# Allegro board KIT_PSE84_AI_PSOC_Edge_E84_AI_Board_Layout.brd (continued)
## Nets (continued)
GND_EARTH: C13.1 J1.SH1 J1.SH2 J1.SH3 J1.SH4 J2.SH1 J2.SH2 J2.SH3 J2.SH4 R7.1
GND_SIGNAL: C1.1 C3.1 C4.1 C5.1 C6.1 C7.1 C8.1 C9.1 C11.1 C12.2 C13.2 C14.2 C16.2 C17.2 C21.2 C28.2 C30.2 C31.2 C35.2 C36.2 C37.2 C38.2 C39.2 C40.2 C41.2 C42.2 C43.2 C44.2 C45.2 C46.2 C47.2 C48.2 C49.2 C50.2 C51.2 C52.2 C53.2 C54.2 C55.2 C56.2 C57.2 C58.2 C59.1 C60.1 C61.2 C62.2 C63.1 C64.2 C65.2 C66.2 C67.2 C68.2 C69.2 C70.2 C71.2 C72.1 C73.2 C74.2 C75.2 C76.2 C77.2 C78.2 C79.2 C80.2 C81.2 C82.2 C83.2 C84.2 C85.2 C86.2 C87.2 C88.2 C89.2 C92.2 C93.2 C94.2 C95.2 C96.2 C97.2 C98.2 C99.2 C100.2 C101.2 C102.2 C103.2 C104.2 C107.2 C108.2 C109.2 C110.2 C111.2 C112.2 C113.2 C114.2 C115.2 C116.2 C118.2 C123.2 C124.2 C126.2 C136.2 C137.2 C138.2 C139.2 C140.2 C141.2 C142.2 C143.2 C144.2 C145.2 C146.2 C147.2 C148.2 C149.2 C150.2 C151.2 C152.2 C153.2 C154.2 C155.2 C156.2 C157.2 C158.2 C159.2 C160.2 C161.2 C162.2 C163.2 C164.2 C165.2 C166.2 C167.2 C168.2 C169.2 C170.2 C171.2 C172.2 C173.2 C174.2 C175.2 C176.2 C177.2 C178.2 C179.2 C180.2 C182.2 C183.2 C184.2 C185.2 C186.2 C189.2 C191.2 C194.2 C196.2 C197.2 C200.2 C203.1 C204.2 C205.2 D1.A D2.A D4.A D15.A J1.A1 J1.A12 J1.B1 J1.B12 J2.A1 J2.A12 J2.B1 J2.B12 J3.2 J3.SH1 J3.SH2 J4.3 J4.5 J4.7 J4.9 J5.6 J7.1 J7.SH1 J7.SH2 J8.SH1 J8.SH2 J10.3 J10.6 J10.9 J10.12 J10.15 J10.SH1 J10.SH2 J12.G1 J12.G2 J12.G3 J14.20 J16.3 J17.4 J17.SH1 J17.SH2 J17.SH3 J17.SH4 L2.1 L3.1 L6.1 L7.1 LED4.K(CATHODE) LED5.K(CATHODE) Q3.1 Q3.4(S) Q7.S Q8.S Q9.S Q10.S Q11.S R3.2 R4.2 R7.2 R11.2 R16.2 R22.1 R24.1 R27.1 R73.1 R77.2 R80.2 R84.2 R86.2 R110.1 R126.1 R135.1 R155.2 R173.1 R187.1 R191.1 R211.1 R212.1 R213.1 R214.1 R215.1 R216.2 SW2.3 SW2.4 SW3.3 SW3.4 TP2.1(TP) TP10.1(TP) TP17.1(TP) TP47.1(TP) U1.A9 U1.B5 U1.B13 U1.C8 U1.C10 U1.C11 U1.C12 U1.C13 U1.D3 U1.D7 U1.D9 U1.D11 U1.D12 U1.D13 U1.E8 U1.E12 U1.F3 U1.G13 U1.H3 U1.H12 U1.J13 U1.K12 U1.L3 U1.L8 U1.L13 U1.N3 U1.N10 U1.R7 U2.5 U2.7 U2.8 U2.9 U2.25 U2.43 U2.45 U2.58 U2.62 U2.63 U2.H U3.B3 U3.C1 U3.E5(VSSQ_2) U4.B3 U5.A1 U5.A2 U5.A3 U5.A4 U5.A5 U5.A6 U5.A7 U5.A8 U5.A9 U5.B3 U5.B4 U5.B8 U5.B9 U5.C9(VSSRF_9) U5.D9 U5.E9 U5.H9 U5.J9 U5.K1 U5.K9 U5.L9 U5.M7 U5.M9 U6.1 U6.7 U7.5 U8.4 U8.5 U9.4 U9.5 U10.4 U10.5 U13.8 U15.3(VSS) U15.H U18.6 U18.7 U19.3 U20.B1 U20.C3 U21.10 U22.4(VSS) U23.3(VSS) U23.H U24.2 U25.10 U25.12 U25.13 U25.19 U25.21 U25.24 U25.26 U25.27 U25.29 U25.39 U25.44 U25.49 U25.51 U25.52 U25.53 U25.55 U25.56 U25.58 U25.59 U25.60 U25.61 U25.66 U25.67 U25.68 U25.69 U25.70 U25.71 U25.72 U26.3(VSS) U26.H U27.3(VSS) U27.H U28.1 U28.16 U28.18 U28.20 U28.25 U28.29 U28.H U29.1 U29.6 U30.3 U31.2 U33.2 U33.5 U34.2 U34.5 U34.H U35.2 U35.5 U36.3 U40.4 Y1.2 Y1.4(GND_2) Y3.2 Y4.G
VBAT_IN: C9.2 C186.1 D15.K(CATHODE) J3.1 TP8.1(TP) U23.4 U23.6
VCC_1V8: C73.1 C75.1 C81.1 C83.1 C89.1 C196.1 FB1.1 FB2.1 FB4.1 FB5.1 FB6.1 FB7.1 J17.3 R124.1 R225.1 TP50.1(TP) U33.1(OUT)
VCC_3V3: C77.1 C191.1 FB3.1 J17.2 TP51.1(TP) U35.1(OUT)
VCC_IN: C3.2 C7.2 C8.2 C14.1 C16.1 L1.1 U23.1 U26.1 U27.1 U29.5 U29.7
VDD_1V8: C5.2 C61.1 C62.1 C63.2 C64.1 C65.1 C66.1 C67.1 C68.1 C70.1 C71.1 C96.1 C97.1 C98.1 C99.1 C111.1 C112.1 C113.1 C114.1 C197.1 C200.1 C204.1 J5.1 R2.1 R5.2 R6.1 R8.2 R9.1 R76.1 R79.1 R85.2 R112.2 R114.2 R123.2 R192.2 R193.2 R194.2 R195.2 R196.2 R203.2 R204.1 R205.1 R208.2 R224.1 TP49.1(TP) U3.B4 U3.D1 U3.E4 U4.B4 U6.6(VDDIO) U6.8 U7.2(VDD) U7.4 U8.2(VDD) U18.5(VDDIO) U18.8 U18.12 U20.B2 U20.B3(VDDIO) U20.C1 U22.3 U28.2 U28.3 U31.5 U34.3(VOUT) U34.8 U40.8(VCCB) Y3.1 Y3.4(VDD) Y4.P(VDD)
VDD_3V3: C27.1 C28.1 C94.1 C95.1 C107.1 C108.1 C109.1 C110.1 C194.1 C203.2 J7.2 J14.19 R15.1 R153.2 R159.2 R188.2 R197.2 R206.2 R207.2 R217.2 TP48.1(TP) U13.11 U25.22 U25.23 U28.17 U28.28 U33.3 U33.4 U40.1
VDD_5V: C6.2 C12.1 C17.1 C21.1 C30.1 C31.1 C101.1 C102.1 C103.1 C104.1 C182.1 C183.1 C184.1 C189.1 C205.1 J16.1 J17.1 LED3.4 R10.1 R174.2 R190.2 R209.2 R210.2 TP12.1(TP) U13.6 U13.7 U13.9(PVIN) U15.6 U21.12 U28.21 U28.24 U29.3(VOUT) U34.4 U34.6 U35.3 U35.4
VDDA_RADAR: C76.1 FB2.2 U5.J1
VDDD_RADAR: C74.1 FB1.2 U5.H1
VDDIO_RADIO: C93.1 R103.1 R104.1 R105.1 R106.1 R107.1 R108.1 R109.1 R203.1 U25.11
VDDLF_RADAR: C78.1 FB3.2 U5.M3
VDDPLL_RADAR: C84.1 FB6.2 U5.M4
VDDRF_RADAR: C85.1 C86.1 C87.1 C88.1 FB7.2 U5.F9 U5.G9 U5.M1
VDDVCO_RADAR: C82.1 FB5.2 U5.M6
A_IO_P13_0: J17.20 U1.G8
A_IO_P13_1: J17.18 U1.G9
A_IO_P13_2: J17.16 U1.G10
A_IO_P13_3: J17.14 U1.F15
A_IO_P13_4: J17.12 U1.G11
A_IO_P13_5: J17.10 U1.G14
A_IO_P13_6: J17.8 U1.H11
A_IO_P13_7: J17.6 U1.H15
A_IO_P15_0: J17.5 U1.L15
A_IO_P15_1: J17.7 U1.K13
A_IO_P15_2: J17.9 U1.M15
A_IO_P15_3: J17.11 U1.K9
A_IO_P15_4: J17.13 U1.N15
A_IO_P15_5: J17.15 U1.K10
A_IO_P15_6: J17.17 U1.P15
A_IO_P15_7: J17.19 U1.K11
ALT_SER_INT_CONFIG_1: R76.2 R77.1 TP66.1(TP) U1.R15
ALT_SER_INT_CONFIG_2: R79.2 R80.1 TP65.1(TP) U1.M12
AMIC1_CTB_INN: C121.2 R132.2 U1.H13
AMIC1_CTB_INP: C116.1 R128.2 R227.2 U1.H10
AMIC1_CTB_OUT: C121.1 C122.1 R133.2 U1.H9
AMIC1_CTB_REF: R227.1 U1.J10
AMIC2_CTB_INN: C129.2 R141.2 U1.J15
AMIC2_CTB_INP: C124.1 R137.2 R228.2 U1.J9
AMIC2_CTB_OUT: C129.1 C130.1 R142.2 U1.K15
AMIC2_CTB_REF: R228.1 U1.J14
AMIC_1V8: C118.1 C126.1 R124.2 R125.1 R134.1 R224.2 U9.2(VDD) U10.2(VDD)
BOOT: R189.1 U1.N8
BT_DEV_WAKE: R106.2 U1.D15 U25.40
BT_HOST_WAKE: R107.2 U1.D14 U25.41
BT_REG_ON: R105.2 U1.E14 U25.8
BT_UART_CTS_MCU_RTS: TP55.1(TP) U1.A14 U25.48
BT_UART_RTS_MCU_CTS: TP56.1(TP) U1.C15 U25.47
BT_UART_RX_MCU_TX: TP53.1(TP) U1.A13 U25.45
BT_UART_TX_MCU_RX: TP54.1(TP) U1.B15 U25.46
DISP_VDD_3V3: C136.1 J10.1 J10.2 R153.1
DSI_CLK_N: J10.11 R66.1
DSI_CLK_P: J10.10 R67.1
DSI_DATA0_N: J10.8 R70.1
DSI_DATA0_P: J10.7 R71.1
DSI_DATA1_N: J10.14 R68.1
DSI_DATA1_P: J10.13 R69.1
ECO_IN: C55.1 U1.B6 Y1.1
ECO_OUT: C56.1 U1.F8 Y1.3
EXT_CLK: R218.2 U1.P4
I2C_SCL_1V8: R32.1 R223.2 U1.H7 U2.38 U6.4 U18.13 U22.2 U28.10
I2C_SCL_3V3: J7.4 J10.5 J14.17 J16.2 R207.1 U1.M9
I2C_SDA_1V8: R31.1 R220.2 U1.J8 U2.39 U6.3 U18.14 U22.1 U28.9
I2C_SDA_3V3: J7.3 J10.4 J14.18 J16.4 R206.1 U1.R9
I2S_TX_FSYNC: U1.E5 U28.6
I2S_TX_MCK: U1.D4 U28.8
I2S_TX_SCK: U1.K7 U28.7
I2S_TX_SD: U1.E4 U28.5
I3C_SCL: R205.2 R222.2 TP71.1(TP) U1.M4
I3C_SDA: R204.2 R221.2 TP72.1(TP) U1.L6
IMU_INT1: U1.L5 U18.4
IMU_INT2: U1.P5 U18.9
JTAG_SEL: R109.2 R110.2 U25.57
KP_USB_DM: J1.A7 J1.B7 R28.1 U19.1
KP_USB_DP: J1.A6 J1.B6 R26.1 U19.2(K2)
KP_VBUS: C4.2 D1.K(CATHODE) J1.A4 J1.A9 J1.B4 J1.B9(VBUS_4) R18.2 TP1.1(TP) U27.4 U27.6
LPO_OUT_2FY: R182.2 U25.30
MAG_INT: U1.R5 U20.A1
MCU_UART_RX_KP3_TX: U1.R2 U2.20
MCU_UART_TX_KP3_RX: R29.1 U1.P2 U2.21
MCU_VDD_3V3: C139.1 C140.1 C141.1 C179.1 C180.1 R154.2 R197.1 U1.B11 U1.D10 U1.R10
MEMORY_RST: R208.1 U1.K5 U3.A4
P5LP1_2: SW3.1 SW3.2 U2.13
P5LP1_4: R30.2 U2.15
P5LP2_2: U2.64
P5LP2_3: U2.65
P5LP2_4: U2.66
P5LP_SIO_VREF: R21.2 R22.2 U2.48
P5LP_SWCLK: TP19.1(TP) U2.12
P5LP_SWDIO: TP20.1(TP) U2.11
P5LP_VCCD: C44.1 C45.1 U2.26 U2.57
P5LP_VDD: C35.1 C36.1 C37.1 C38.1 C39.1 C40.1 C41.1 C42.1 C46.1 C47.1 C48.1 C49.1 C50.1 C51.1 R18.1 R25.1 TP16.1(TP) U2.17 U2.24 U2.35 U2.44 U2.52 U2.59 U2.67
P5LP_XRES: TP18.1(TP) U2.10(X\R\E\S\)
P11_1: TP70.1(TP) U1.E11 U40.7
P11_1_IN_3V3: J14.13 U40.2
P16_0: J14.6 U1.M11
P16_1: J14.5 U1.R13
P16_2: J14.8 U1.N11
P16_3: J14.7 U1.L11
P16_4: J14.10 U1.P11
P16_5: J14.9 U1.L10
P16_6: J14.12 U1.R11
P16_7: J14.11 U1.M10
P17_2: J14.15 U1.R8
P17_3: J14.16 U1.P9
P17_4: J14.14 U1.P8
P17_5: J14.1 J14.3 U1.N9
P17_7: J14.2 J14.4 U1.L9
PDM_CLK: R88.2 R92.2 U1.E7
PDM_DATA: R87.2 R91.2 U1.G6
PE84_RST_L: C58.1 J4.10 R72.2 SW2.1 SW2.2 U1.D8 U2.3
PE84_SWCLK: J4.4 R200.2 U1.R6 U2.47
PE84_SWDIO: J4.2 R199.2 U1.P6 U2.46
PE84_SWO: J4.6 R201.2 U1.M6
PE84_TDI: J4.8 R202.2 U1.N6
PE84_USB_CC1: J2.A5 U21.1 U36.1
PE84_USB_CC2: J2.B5 U21.2 U36.2(K2)
PE84_USB_CF: R2.2 TP3.1(TP) U1.K8 U21.6(\V\C\O\N\N\_\F\A\U\L\T\)
PE84_USB_DIR: R6.2 TP5.1(TP) U1.M5 U21.11
PE84_USB_DM: J2.A7 J2.B7 U1.P7 U30.1
PE84_USB_DP: J2.A6 J2.B6 U1.N7 U30.2(K2)
PE84_USB_ID: R9.2 TP7.1(TP) U1.N5 U21.9 U31.1
PE84_USB_OUT1: R8.1 TP6.1(TP) U1.L4 U21.7
PE84_USB_OUT2: R5.1 TP4.1(TP) U1.N4 U21.8
PE84_VBUS: C1.2 C11.2 C185.1 D2.K(CATHODE) J2.A4 J2.A9 J2.B4 J2.B9(VBUS_4) R1.2 R219.2 TP9.1(TP) U15.1 U26.6
PE84_VCCD: C152.1 C165.1 C166.1 C167.1 C168.1 C169.1 L5.2 TP45.1(TP) U1.B1 U1.B9 U1.B12 U1.E9 U1.F11 U1.H4 U1.M8
PE84_VDDA: C146.1 C147.1 C148.1 C149.1 C170.1 FB9.2 U1.G12 U1.H14 U1.J11 U1.J12 U1.L12
PE84_VTARG: C54.1 C138.1 C150.1 C151.1 C175.1 D4.K(CATHODE) FB8.1 FB10.2 FB11.2 J4.1 R21.1 R23.1 R29.2 R31.2 R32.2 R72.1 R196.1 R198.1 R199.1 R200.1 R201.1 R202.1 R226.1 U1.A10 U1.A11 U1.B10 U1.D6
PSEN_INT: R84.1 U1.E10 U6.5
RF_OUT: C90.1 C198.1 U25.50
ROSC_IN_80MHZ: R102.2 U5.M2
RSPI_CLK: U1.L7 U5.B1
RSPI_CS: U1.C3 U5.G1
RSPI_IRQ: U1.N12 U5.C1
RSPI_MISO: U1.K6 U5.E1
RSPI_MOSI: U1.C5 U5.D1
RXRES_L: R101.1 U1.R12
SERIAL_INT0: J5.5 R192.1 U1.L14
SERIAL_INT1: J5.4 R193.1 U1.M13
SERIAL_INT2: J5.3 R194.1 U1.M14
SERIAL_INT3: J5.2 R195.1 U1.N13
SMIF0_CLKP: R61.1 U4.B2
SMIF0_CS: R112.1 U1.K4 U4.C2
SMIF0_DATA0: R45.1 U4.D3
SMIF0_DATA1: R47.1 U4.D2
SMIF0_DATA2: R49.1 U4.C4
SMIF0_DATA3: R51.1 U4.D4
SMIF1_CLKN: R63.2 U3.B1
SMIF1_CLKP: R62.2 U3.B2
SMIF1_CS: R114.1 U1.C4 U3.A3
SMIF1_DATA0: R46.2 U3.D3
SMIF1_DATA1: R48.2 U3.D2
SMIF1_DATA2: R50.2 U3.C4
SMIF1_DATA3: R52.2 U3.D4
SMIF1_DATA4: R54.2 U3.D5
SMIF1_DATA5: R56.2 U3.E3
SMIF1_DATA6: R58.2 U3.E2
SMIF1_DATA7: R60.2 U3.E1
SMIF1_RWDS: R65.2 U3.C3
USB_DEV_EN: Q3.5 R191.2 R219.1 U26.4 U31.4(Y)
USB_HOST_EN: Q3.2 R173.2 U15.4 U31.3 U31.6
USB_V_SENSE: R25.2 R27.2 U2.19
USER_BTN: C57.1 R198.2 SW1.1 SW1.2 U1.P3
USER_LED1: Q7.G R211.2 U1.C14
USER_LED2: Q8.G R212.2 U1.B14
USER_LED_RGB_B: Q11.G R215.2 U1.P12
USER_LED_RGB_G: Q10.G R214.2 U1.R14
USER_LED_RGB_R: Q9.G R213.2 U1.P13
USR_RGB_B: Q11.D R165.2
USR_RGB_G: Q10.D R157.1
USR_RGB_R: Q9.D R156.1
VTARG_MEAS: R23.2 R24.2 U2.32
WCO_IN: C60.2 U1.H8 Y2.1
WCO_OUT: C59.2 U1.G7 Y2.2
WL_BT_DEV_WAKE: R103.2 U1.E15 U25.5
WL_HOST_WAKE: R104.2 U1.F13 U25.2
WL_REG_ON: R108.2 U1.F14 U25.9(WL_REG_ON)
WL_SDIO_CLK: R38.2 U25.20
WL_SDIO_CMD: R33.2 U25.15
WL_SDIO_DATA0: R37.2 U25.14
WL_SDIO_DATA1: R36.2 U25.16
WL_SDIO_DATA2: R35.2 U25.17
WL_SDIO_DATA3: R34.2 U25.18
N17461053: TP21.1(TP) U5.M5
N17461288: C72.2 U5.L1
N17462113: C79.1 C80.1 FB4.2 U24.4(VCC)
N17462137: R102.1 U24.3
N17489317: R73.2 SW1.3 SW1.4
N17506591: R85.1 R86.1 U18.1
N17580471: C43.1 U2.53
N17581080: C52.1 U2.42
N17581130: R26.2 U2.22
N17581131: R28.2 U2.23
N17581135: C53.1 U2.31
N17604769: R101.2 U5.F1
N17606878: LED4.A R30.1
N17691977: C92.1 L4.1 U25.25
N17691999: L4.2 U25.28
N17694386: J8.1 U28.22 U28.26
N17694402: J8.2 U28.19 U28.23
N17694449: C100.1 R123.1 U28.31(\R\E\S\E\T\)
N17694464: TP22.1(TP) U28.27
N17694501: TP23.1(TP) U28.30
N17694590: C105.1 TP24.1(TP)
N17694592: C105.2 U28.13
N17694611: C106.2 U28.14
N17694617: C106.1 TP25.1(TP)
N17695662: C115.1 C119.1 R125.2 R126.2 R127.2 R128.1
N17695725: C117.2 R127.1
N17695747: R129.1 U10.1
N17695749: C117.1 R129.2
N17695799: R130.1 U10.3
N17695801: C120.1 R130.2
N17695803: C120.2 R131.1
N17695815: C119.2 C122.2 R131.2 R132.1 R133.1
N17695981: C123.1 C127.1 R134.2 R135.2 R136.2 R137.1
N17696044: C125.2 R136.1
N17696066: R138.1 U9.1
N17696068: C125.1 R138.2
N17696118: R139.1 U9.3
N17696120: C128.1 R139.2
N17696122: C128.2 R140.1
N17696134: C127.2 C130.2 R140.2 R141.1 R142.1
N17699019: C137.1 C142.1 C143.1 C144.1 C145.1 FB8.2 U1.A7 U1.B8 U1.F7 U1.G4 U1.P10
N17699233: FB9.1 R225.2 R226.2
N17699382: L5.1 U1.A12
N17699478: C153.1 C154.1 R154.1 U1.M7
N17699488: C155.1 TP46.1(TP) U1.K14
N17701248: C156.1 C157.1 C158.1 U1.A8(VLDO_SRAM) U1.F12 U1.K3
N17701334: C159.1 U1.C9
N17701356: C160.1 C161.1 C162.1 C163.1 C164.1 FB10.1 U1.A6 U1.B2 U1.E6 U1.E13 U1.N14 U1.R3
N17701674: C171.1 C172.1 C173.1 C174.1 FB11.1 U1.E3 U1.G3 U1.J3 U1.M3
N17701770: R155.1 U1.J6
N17701786: C176.1 C177.1 C178.1 U1.B7 U1.C6 U1.C7
N17708163: R33.1 U1.J5
N17708171: R34.1 U1.F5
N17708201: R35.1 U1.F4
N17708259: R36.1 U1.G5
N17708293: R37.1 U1.D5
N17708327: R38.1 U1.H5
N17708399: TP69.1(TP) U1.P14
N17708861: R45.2 U1.N2
N17708863: R46.1 U1.C2
N17708893: R47.2 U1.P1
N17708895: R48.1 U1.C1
N17708925: R49.2 U1.N1
N17708927: R50.1 U1.D2
N17708957: R51.2 U1.M2
N17708959: R52.1 U1.D1
N17708991: R54.1 U1.F2
N17709023: R56.1 U1.E2
N17709055: R58.1 U1.G2
N17709075: R60.1 U1.H2
N17709105: R61.2 U1.M1
N17709107: R62.1 U1.E1
N17709123: R63.1 U1.F1
N17709155: R65.1 U1.H1
N17709188: R66.2 U1.A4
N17709192: R67.2 U1.A5
N17709220: R68.2 U1.A3
N17709224: R69.2 U1.A2
N17709256: R70.2 U1.B4
N17709266: R71.2 U1.B3
N17713209: L1.2 U29.2
N17713383: R10.2 R11.1 U29.4
N17787194: J1.A5 R4.1
N17787196: J1.B5 R3.1
N17852597: R1.1 U21.5
N17861601: LED5.A R159.1
N17865809: U13.2 U13.3 U13.10
N17865831: C27.2 R15.2 R16.1 U13.5
N17879800: U34.1 U34.7
N17892556: R218.1 TP52.1(TP) Y3.3
N17899696: R187.2 R188.1 R189.2
N17920449: ANT1.1 C91.2 L3.2
N17920453: C90.2 C91.1 L2.2
N17920674: C198.2 C199.1 L6.2
N17920680: C199.2 J12.S(SIG) L7.2
N17936697: D11.A R174.1
N17936707: D11.K(CATHODE) Q3.6
N17937120: D14.A R190.1
N17937130: D14.K(CATHODE) Q3.3
N17947353: R182.1 Y4.O
N17989965: R88.1 U8.3
N17989977: R87.1 U8.1
N17990624: R92.1 U7.3
N17990639: R91.1 U7.1
N18038435: LED1.A R209.1
N18038437: LED2.A R210.1
N18038455: LED1.K(CATHODE) Q7.D
N18038457: LED2.K(CATHODE) Q8.D
N18039037: LED3.1(RED) R156.2
N18039056: LED3.2 R157.2
N18039072: LED3.3 R165.1
N18042757: R216.1 R217.1 U40.5
N18094677: R220.1 R221.1 U20.A2
N18094686: R222.1 R223.1 U20.A3
N18095156: C69.1 U20.C2

Pads without a net: ANT1 2; J1 A8 B8; J2 A8 B8; U1 F6 F9 F10 H6 J1 J2 J4 J7 K1 K2 L1 L2 R4; U2 1 2 4 6 14 16 18 27 28 29 30 33 34 36 37 40 41 49 50 51 54 55 56 60 61 68; U3 A2 A5 B5 C2 C5; U4 A2 A3 A4 A5 B1 B5 C1 C3 C5 D1 D5 E1 E2 E3 E4 E5; U6 2; U13 1 4; U15 2 5; U18 2 3 10 11; U21 3 4; U23 2 5; U24 1; U25 1 3 4 6 7 31 32 33 34 35 36 37 38 42 43 54 62 63 64 65; U26 2 5; U27 2 5; U28 4 11 12 15 32; U40 3 6; Y4 N

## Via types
v1: diameter 0.406, hole 0.203, TOP to BOTTOM, 208 vias
v2: diameter 0.457, hole 0.203, TOP to BOTTOM, 222 vias
v3: diameter 0.508, hole 0.254, TOP to BOTTOM, 318 vias
v4: diameter 0.45, hole 0.2, TOP to BOTTOM, 5 vias

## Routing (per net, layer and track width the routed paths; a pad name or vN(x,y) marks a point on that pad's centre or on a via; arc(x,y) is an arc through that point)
GND_EARTH: length 39.4
  TOP w0.305: 5.31,1.94 J2.SH3 ; J2.SH3 6.01,3.05 ; J2.SH3 6.72,1.94 ; J2.SH3 6.01,0.84 ; 6.01,4.87 J2.SH1 5.31,6.12 ; J2.SH4 15.36,1.94 ; J2.SH4 13.95,1.94 ; J2.SH4 14.65,0.84 ; J2.SH4 14.65,3.05
  BOTTOM w0.305: 29.28,6.12 J1.SH2 ; J1.SH2 29.98,4.87 ; J1.SH2 30.69,6.12 ; J1.SH2 29.98,7.38 ; J2.SH1 6.72,6.12 ; J2.SH1 6.01,7.38 ; J2.SH1 5.31,6.12 ; J2.SH1 6.01,4.87 ; J2.SH2 14.65,7.38 ; J2.SH2 15.36,6.12 ; J2.SH2 14.65,4.87 ; J2.SH2 13.95,6.12 ; 21.34,4.87 J1.SH1 ; J1.SH1 22.05,6.12 ; J1.SH1 21.34,7.38 ; J1.SH1 20.64,6.12 ; 6.01,0.84 J2.SH3 ; J2.SH3 5.31,1.94 ; J2.SH3 6.72,1.94 ; J2.SH3 6.01,3.05 ; 20.64,1.94 J1.SH3 ; J1.SH3 21.34,0.84 ; J1.SH3 21.34,3.05 ; J1.SH3 22.05,1.94 ; 14.65,0.84 J2.SH4 ; J2.SH4 14.65,3.05 ; J2.SH4 13.95,1.94 ; J2.SH4 15.36,1.94 ; J1.SH4 29.98,3.05 ; J1.SH4 30.69,1.94 ; J1.SH4 29.28,1.94 ; J1.SH4 29.98,0.84
GND_SIGNAL: length 385.1
  TOP w0.15: U1.D9 25.84,35.26 v1(25.86,35.26) ; v1(23.97,35.27) 23.97,35.24 U1.D7 ; U1.C10 v1(26.52,35.94) ; U1.L8 v1(25.22,30.09) ; U1.E12 v1(27.82,34.64) ; U1.C12 v1(27.82,35.94) ; U1.D11 v1(27.17,35.29) ; U1.E8 v1(25.22,34.64) ; U1.G13 28.45,33.32 v1(28.45,33.38) ; U1.K12 v1(27.82,30.74) ; U1.F3 v1(21.32,33.99) ; U1.D3 v1(21.32,35.29) ; U1.B5 22.62,36.59 v1(22.62,36.59) ; U1.D13 v1(28.47,35.29) ; U1.C11 v1(27.17,35.94) ; U1.H3 v1(21.32,32.04) ; U1.N10 v1(26.52,28.79) ; U1.C13 v1(28.47,35.94) ; U1.J13 v1(28.47,31.39) ; U1.C8 v1(25.22,35.94) ; U1.L3 v1(21.32,30.09) ; U1.D12 v1(27.82,35.29) ; U1.N3 v1(21.32,28.79) ; U1.B13 v1(28.47,36.59) ; U1.H12 v1(27.82,32.04) ; U1.L13 v1(28.47,30.09)
  TOP w0.178: R86.2 22.53,21.94 22.72,22.14 v3(22.72,22.68) ; C86.2 21.59,18.29 22.36,19.06 22.41,19.06 v3(22.72,19.37) ; C200.2 28.81,50.42 28.8,50.42 28.8,50.28 28.45,49.92 28.45,49.1 ; C185.2 12.92,16.21 12.95,16.19 C1.1 13.9,16.19 13.95,16.14 U15.3 ; C185.2 12.22,16.21 11.97,16.45 v3(11.5,16.45) ; C185.2 12.42,15.47 13.31,14.58 U31.2 ; C5.1 16.18,14.33 v3(15.89,14.05)
  TOP w0.229: C76.2 25.55,20.83 v3(25.81,20.58) ; v3(22.48,12.57) 22.07,12.57 21.84,12.35 C89.2 ; U6.7 33.74,20.29 v3(34.04,19.99) ; C77.2 17.53,15.5 17.48,15.55 17.48,15.64 v3(17.41,15.71) ; U25.56 23.52,46.19 v3(23.92,45.79) ; 30.54,17.83 30.1,17.39 U5.A3 U5.B3 ; J3.SH2 3.65,9.73 v3(3.93,10.01) ; v3(19.56,16.71) 19.05,16.71 U24.2 ; C73.2 28.88,22.55 28.5,22.94 27.89,22.94 27.86,22.96 C75.2 27.84,22.63 27.56,22.35 26.14,22.35 25.91,22.58 v3(25.78,22.58) ; v3(29.75,13.11) 29.41,13.44 29.41,14.1 29.12,14.39 U5.A9 ; v3(26.99,13.72) 26.93,13.78 U5.D9 U5.E9 ; v4(7.42,27.53) 7.14,27.81 C104.2 ; v3(20.95,50.67) 21.32,50.31 U25.52 ; U5.B8 U5.A7 28.83,15.39 29.08,15.64 v3(29.08,16.11) 28.86,15.89 U5.A6 U5.A5 ; LED4.K v3(35.2,5.44) ; v3(30.4,17.78) 29.9,17.78 29.29,18.39 U5.A1 U5.A2 ; C68.2 16.27,25.2 16.04,25.43 v1(15.62,25.43) ; C87.2 25.33,11.24 v3(25.78,10.8) 25.78,10.85 26.13,11.2 C88.2 ; C93.2 20.85,43.46 21.07,43.69 U25.12 ; v3(25.96,50.85) 25.63,50.52 25.53,50.52 25.32,50.3 U25.44 ; v3(19.38,5.03) 19.16,5.25 Q3.1 ; v3(16.94,54.28) 17.37,54.71 J10.3 ; U22.4 32.54,14.65 32.18,15.01 C71.2 ; v3(34.68,51.91) 34.57,51.79 C126.2 ; 7.14,25.81 6.59,25.81 6.31,26.08 v3(5.84,26.08) ; C118.2 4.17,52.13 4.57,51.73 v3(4.57,51.26) ; 8.76,24.74 9.27,24.74 9.27,24.43 9.4,24.31 v3(9.4,24.24) ; U25.12 21.47,43.47 21.32,43.32 U25.13 ; U25.12 21.82,43.69 v3(22.62,44.49) 22.42,44.69 U25.10 ; C12.2 13.38,8.46 v3(13.87,7.98) ; v3(21.56,51.11) 21.56,50.91 21.82,50.66 U25.51 ; v3(21.95,14.17) 22.17,14.39 U5.M9 U5.M7 ; J10.6 14.37,57.05 v3(13.69,57.74) ; v3(13.18,25.38) 12.83,25.02 11.63,25.02 C58.2 ; U5.J9 U5.H9 24.77,14.23 v3(24.77,13.85) ; v1(15.62,26.95) 15.67,27 C69.2 ; v3(16.95,7.71) 16.95,7.61 16.86,7.52 Q3.4 ; U5.B4 U5.A4 28.83,16.89 28.93,16.79 v3(28.93,16.77) ; v3(22.72,20.64) 22.72,20.74 23.08,21.1 C72.1 ; v3(24.25,19.37) 23.91,19.04 23.91,18.76 23.93,18.74 U5.K1 ; C60.1 30.22,39.19 30.75,38.66 31.24,38.66 v3(31.57,38.33) ; v3(19.97,11.66) 20.13,11.49 C82.2 ; v3(15.21,21.77) 15.21,22.06 15.44,22.29 C57.2 ; v3(25.22,44.49) 25.22,43.77 25.32,43.67 U25.21 ; U25.55 23.52,46.69 v3(23.92,47.09) ; 20.95,16.36 C78.2 ; SW2.3 14.67,27.56 14.86,27.37 v1(14.86,26.95) ; SW2.3 SW2.4 ; SW2.3 14.97,28.38 15.28,28.69 16.66,28.69 16.89,28.46 C67.2 17.32,27.99 17.45,27.86 U20.B1 ; LED5.K 4.55,7.65 v3(5.08,8.18) ; v1(14.5,17.59) 14.97,18.06 C6.1 15.27,18.01 ; U25.29 26.72,44.69 v3(26.52,44.49) 26.52,44.02 26.82,43.72 U25.24 ; v3(19.71,10.16) C83.2 18.95,10.16 18.22,9.43 C81.2 ; Y1.4 20.83,40.58 20.8,40.61 20.13,40.61 20.09,40.65 ; U20.C3 16.69,25.93 v1(15.62,25.93) ; C97.2 10.85,40.15 11.97,39.03 v3(12.73,39.03) 12.73,39.8 12.67,39.85 C96.2 ; v3(19.36,24.8) 19.36,24.77 ; 19.36,24.77 19,24.41 C64.2 19,24.09 18.6,23.7 U18.7 ; 19.36,24.77 19.7,24.42 C63.1 19.7,24.31 19.13,23.73 19.13,23.26 U18.6 ; 32.26,53.19 v3(32.26,53.19) ; v3(35.22,20.94) U6.1 ; U3.B3 11.65,35.8 11.34,36.11 v1(11.33,36.11) ; R213.1 30.99,13.25 Q9.S ; U5.A9 U5.B9 U5.C9 ; U5.A9 U5.A8 ; v3(24.96,41.24) 24.96,40.8 25.2,40.56 C177.2 25.59,40.38 25.59,40.39 C95.2 C92.2 27.64,40.26 27.95,40.26 v3(28.28,39.93) 28.3,39.91 28.3,39.9 28.4,39.79 C59.1 27.64,39.22 27.28,39.57 C151.2 C158.2 ; J10.15 5.37,54.64 5.55,54.46 v3(6.02,54.46) ; U25.39 27.82,51.02 ; v3(28.55,43.61) 28.35,43.61 28.27,43.69 U25.27 ; U5.L9 U5.K9 23.93,13.94 v3(24.64,13.23) ; v3(23.92,44.49) 24.32,44.09 U25.19 ; J10.9 11.37,56.6 12.04,57.26 v3(12.04,57.74) ; C180.2 26.68,24.39 26.94,24.65 27.37,24.65 27.46,24.56 v3(27.93,24.56) ; C4.1 27.88,9.22 v3(28.13,8.97) ; Q7.S 31.69,8.31 31.97,8.03 R211.1 31.97,7.03 v3(32.12,6.89) ; Y1.2 23.47,39.58 23.72,39.83 C56.2 24.36,39.83 24.59,39.6 C178.2 24.59,38.69 24.39,38.48 v3(22.12,38.48) ; 20.09,40.65 20.09,40.9 19.86,41.13 v3(19.78,41.13) ; 20.09,40.65 C55.2 ; 10.23,19.49 v3(10.7,19.49) ; v3(28.27,41.83) 27.82,42.29 U25.26 ; J10.12 8.37,54.56 7.84,54.03 v3(7.21,54.03) ; v3(20.32,14.6) 20.32,14.64 20.55,14.87 C84.2 ; J10.SH2 4.37,60.31 4.56,60.5 v3(5.21,60.5) ; v3(6.91,35.05) C99.2 7.08,34.52 7.36,34.8 U3.C1 ; U25.49 22.82,49.3 22.62,49.1 v3(22.62,48.39) ; C85.2 v3(25,10.84) ; J10.SH1 v3(20.37,60.6)
  TOP w0.254: U1.A9 v1(25.87,37.24)
  TOP w0.305: 1.58,21.81 J14.20 1.58,19.85 ; J5.6 34.42,44.64 ; J5.6 34.42,42.63 ; J5.6 33.41,43.64
  L02_GND w0.089: 28.83,31.04 28.83,30.92 28.8,30.89 28.8,30.63 28.83,30.6 28.83,30.51 ; 28.83,34.9 28.79,34.87 28.79,33.67 28.83,33.63 ; 28.85,31.65 28.99,31.65 29.02,31.68 29.28,31.68 29.31,31.65 29.54,31.65 ; 22.2,36.91 22.11,36.91 22.1,36.92 21.83,36.92 21.81,36.91 21.46,36.91 ; 26.21,36.83 26.19,36.81 26.19,36.21 ; 25.55,30.43 26.37,30.43 26.4,30.4 27.4,30.4 ; 27.38,31.09 27.38,31.14 27.49,31.25 27.49,31.66 27.58,31.75 ; 27.41,29.11 26.92,29.11 ; 28.14,36.93 28.14,37.57 ; 26.15,29.14 25.73,29.14 25.54,29.33 25.54,29.75 ; 27.48,34.31 26.9,34.31 26.9,34.32 ; 23.09,36.91 24.18,36.91 ; 25.63,36.86 25.54,36.77 25.54,36.38 25.63,36.3 ; 23.05,36.26 24.17,36.26 ; 28.14,34.32 28.14,33.71 ; 26.84,27.18 26.82,27.15 ; 29.43,34.96 28.98,34.96 28.93,34.9 ; 26.15,28.46 24.96,28.46 ; 26.94,28.46 27.55,28.46 ; 22.19,36.26 21.63,36.26
  L02_GND w0.102: 28.14,29.06 28.14,29.23 28.16,29.25 28.16,29.52 28.14,29.55 28.14,29.74 ; 28.04,28.45 28.83,28.45
  L02_GND w0.152: 22.75,36.59 v1(22.62,36.59) ; 27.2,27 27.79,27.59 ; 28.36,27.71 29.01,27.71
  L02_GND w0.305: J5.6 34.42,44.64 ; J5.6 34.42,42.63 ; J5.6 33.41,43.64 ; 1.58,19.85 J14.20 ; J14.20 2.56,20.83 ; J14.20 1.58,21.81
  L03_SIG1 w0.229: v4(8.89,29.01) 8.89,30.68 7.47,32.11 v3(6.17,32.11)
  L04_SIG2 w0.381: v3(1.4,54.33) 3.63,56.57 17.57,56.57 18.71,57.71 22.19,57.71 22.57,57.33 22.57,55.92 23.19,55.3 23.19,54.69 23.62,54.26 32.35,54.26 32.52,54.43 v3(33.07,54.43)
  L05_PWR w0.305: J5.6 34.42,44.64 ; J5.6 33.41,43.64 ; J5.6 34.42,42.63
  BOTTOM w0.089: v1(28.47,31.39) 28.78,31.7 29.57,31.7 29.66,31.79 C149.2 30.14,32.06 30.43,31.76 C155.2
  BOTTOM w0.15: 27.64,4.12 v3(27.64,4.01) ; U8.4 4.38,7.91 4.65,8.18 v3(5.08,8.18)
  BOTTOM w0.152: v3(31.85,28.83) 32.29,28.39 J17.SH2 32.78,28.39 32.9,28.27 32.9,28.13 32.93,28.1 32.93,27.75 32.94,27.75 32.94,27.67 32.78,27.51 J17.4
  BOTTOM w0.178: C36.2 19.3,20.65 19.3,20.64 U2.43 ; C53.2 22.47,14.5 22.15,14.17 21.96,14.17 v3(21.95,14.17) ; C53.2 22.11,14.68 22.09,14.66 R24.1 ; C53.2 22.75,14.68 23.25,15.17 C44.2 ; C38.2 C37.2 ; v3(25.81,20.58) 26.28,21.04 U2.8 ; v3(22.72,22.68) 21.49,21.44 U2.45 ; U2.58 23.45,25.58 23.62,25.75 C45.2 ; U2.25 24.65,15.63 24.55,15.54 C40.2 C39.2 24.55,14.11 24.77,13.89 v3(24.77,13.85) ; C51.2 C50.2 27.3,26.59 27.23,26.52 v3(27.18,26.52) ; C46.2 v3(21.34,25.53) ; v3(25.77,19.37) 27.04,20.64 U2.9 ; 35.26,28.88 v2(35.26,28.89) ; U2.5 26.69,22.24 26.35,22.58 v3(25.78,22.58) ; R212.1 26.66,8.08 26.54,8.21 25.6,8.21 25.21,8.59 Q8.S ; C9.1 8.69,15.21 v3(8.46,14.97) ; v3(24.25,20.64) 25.05,21.44 U2.7 ; C48.2 24.86,26.51 24.87,26.49 C49.2
  BOTTOM w0.229: v3(10.7,19.49) 10.46,19.25 C7.1 10.13,18.85 10.33,18.65 U23.3 ; v3(28.13,8.97) 28.13,9.59 27.9,9.82 SW3.4 ; v3(14.3,50.7) 14.12,50.52 C204.2 ; C160.2 29.11,26.94 28.76,26.59 C51.2 ; v3(34.06,13.91) 33.96,14 R215.1 33.06,14 32.89,13.83 32.88,13.83 32.58,13.53 Q11.S ; v3(13.18,25.38) 13.18,25.94 C113.2 ; v3(19.38,5.03) 19.38,5.5 19.19,5.69 R173.1 ; v3(31.54,33.88) 31.29,33.88 31.06,33.66 C146.2 ; U28.25 7.14,30.11 6.93,30.32 C102.2 6.93,31.58 6.74,31.77 6.5,31.77 v3(6.17,32.11) ; v3(35.22,20.94) 34.87,20.6 C62.2 ; C36.2 C35.2 18.02,19.92 C52.2 ; C174.2 20.77,31.46 20.42,31.8 20.08,31.8 C157.2 20.07,31.93 20.3,32.16 21.19,32.16 21.31,32.03 v1(21.32,32.04) ; C43.2 22.21,26.59 23.44,26.59 v3(23.47,26.63) 23.62,26.48 C45.2 ; U40.4 v3(15.9,46.91) ; C41.2 C42.2 ; Y3.2 31.97,38.72 v3(31.57,38.33) 31.57,37.8 32.08,37.29 C139.2 ; C145.2 20.96,32.77 20.73,33 20.73,33.76 20.96,33.99 v1(21.32,33.99) ; R84.2 C65.2 34.01,20.02 34.03,19.99 v3(34.04,19.99) ; 24.56,27.53 C154.2 ; v3(5.28,27.15) 5.41,27.28 U28.20 6.71,27.28 6.96,27.53 v4(7.42,27.53) 7.42,26.06 7.14,25.78 U28.16 7.14,24.53 7.13,24.52 C108.2 ; C138.2 26.01,39.43 25.79,39.65 C150.2 24.92,40.07 25.11,40.26 25.11,40.63 24.96,40.77 v3(24.96,41.24) ; Q10.S 33.76,15.3 33.96,15.5 R214.1 v3(35.23,15.5) ; C203.1 17.04,50.86 v3(17.17,50.99) ; C28.2 18.49,30.05 17.91,30.63 v3(17.91,31.04) ; C114.2 C112.2 12.85,29.15 13.39,29.68 v3(13.39,30.68) 13.16,30.91 C111.2 11.85,30.91 11.65,31.12 C100.2 ; R187.1 22.21,44.08 v3(22.62,44.49) ; v3(23.92,47.09) 23.92,46.81 23.69,46.58 R110.1 ; v3(16.38,4.9) TP17.1 17.32,4.19 R7.2 17.62,4.16 17.91,4.44 C13.2 ; U30.3 11.13,6 11.36,5.78 v3(11.36,5.67) ; v3(15.89,14.05) 16.01,14.17 C80.2 ; v3(28.55,43.61) 28.55,43.48 C94.2 ; SW3.3 31.41,9.11 31.52,9 v3(31.52,8.89) 31.29,8.66 C70.2 ; v3(5.84,26.08) 6.04,26.28 U28.18 ; v1(25.22,35.94) 25.05,35.94 24.69,36.29 C137.2 24.48,36.81 C143.2 ; v1(25.22,34.64) 24.71,34.64 24.53,34.45 C142.2 ; C109.2 9.01,31.65 8.86,31.49 C110.2 8.86,31.09 9.14,30.81 U28.29 9.14,29.26 v4(8.89,29.01) ; C176.2 24.05,35.16 23.97,35.24 v1(23.97,35.27) ; v3(18.54,31.78) 18.54,31.8 18.77,32.03 R155.2 ; R135.1 27.02,51.5 v3(26.62,51.11) ; v1(24.74,9.63) 24.74,9.19 24.57,9.02 C194.2 ; C38.2 19.16,17.43 19.56,17.03 v3(19.56,16.71) ; v3(26.52,44.49) 26.57,44.54 R80.2 ; v1(21.32,35.29) 20.44,35.29 20.12,35.6 C161.2 ; v3(8.9,8.3) 9.37,8.3 9.45,8.38 R11.2 ; U28.1 v3(11.29,29.8) ; R16.2 19.03,26.23 19.2,26.06 C47.2 19.53,26.56 v3(19.61,26.65) 19.97,27 C163.2 ; R22.1 18.81,24.45 19.13,24.77 19.32,24.77 v3(19.36,24.8) ; R126.1 v3(9.78,51.16) ; 17.51,7.72 17.49,7.72 17.48,7.71 v3(16.95,7.71) ; C153.2 24.8,30.5 v1(25.22,30.09) ; v1(24.74,8.31) 24.74,8.33 25,8.59 Q8.S ; v1(26.52,28.79) 26.52,28.72 C144.2 ; C152.2 27.48,41.35 28.04,41.35 28.27,41.58 v3(28.27,41.83) 28.63,42.19 C61.2 30.74,42.22 ; U19.3 25.98,6 v3(26.39,5.59) ; U4.B3 v3(12.73,39.03) ; R3.2 27.03,5.74 v3(27.23,5.54) ; v3(22.12,38.48) 22.12,38.48 22.37,38.73 C164.2 ; v3(16.94,54.28) 17.27,54.61 17.46,54.61 17.85,55.01 C136.2 ; 21.72,52.63 v3(21.72,52.64) ; v3(33.76,24.14) 34.07,23.84 J17.SH3 ; C11.1 16.46,18.8 16.34,18.92 v3(16.34,19.05) ; J7.SH1 v3(16.35,61.26) ; J7.SH2 v3(21.95,61.21) ; U36.3 v3(11.84,3.94) ; R4.2 v3(24.28,5.64) ; J7.1 v3(17.65,60.2) ; v3(16.31,34.8) 16.45,34.66 16.81,34.66 16.83,34.68 C98.2 ; v3(12.59,19.31) 12.73,19.18 C8.1 13.13,18.67 13.18,18.71 U26.3 ; 30.26,15.23 v3(30.4,15.23)
  BOTTOM w0.254: J17.SH4 31.88,23.84 v3(31.67,23.62)
  BOTTOM w0.305: 34.42,42.63 J5.6 ; J5.6 33.41,43.64 ; J5.6 34.42,44.64 ; J14.20 2.56,20.83 ; J14.20 1.58,21.81 ; J14.20 1.58,19.85
  BOTTOM w0.381: v2(35.26,28.89) 35.14,28.77 J17.SH1
  vias: v1(9.2,17.37) v1(9.63,21.9) v1(9.63,20.88) v1(10.47,17.37) v1(14.12,32.49) v1(14.6,18.86) v1(15.14,17.02) v1(15.14,16.26) v1(15.62,26.44) v3(1.57,5.16) v3(2.11,56.44) v3(3.3,15.16) v3(3.58,59.97) v3(4.57,18.21) v3(5.76,21.45) v3(5.8,20.84) v3(5.87,8.59) v3(6.07,58.29) v3(6.48,60.48) v3(7.44,58.19) v3(8.05,60.5) v3(8.07,36.4) v3(8.81,60.1) v3(9.09,10.16) v3(10.54,51.61) v3(10.52,10.03) v3(11.1,60.12) v3(11.61,11.66) v3(12.14,1.53) v3(12.31,2.65) v3(12.47,21.79) v3(13.26,54.51) v3(14.14,45.37) v3(14.48,8) v3(15.04,49.68) v3(15.82,11.51) v3(15.98,24.05) v3(16.03,21.77) v3(16.43,11.53) v3(17.35,8.18) v3(17.91,49.79) v3(17.86,11.86) v3(18.47,50.98) v3(18.96,12.11) v3(19.15,50.9) v3(20.19,15.88) v3(21.18,8.1) v3(21.89,7.67) v3(23.92,48.39) v3(24.25,22.68) v3(24.49,25.43) v3(25.22,48.39) v3(25.22,47.09) v3(25.22,45.79) v3(25.83,52.66) v3(26.52,48.39) v3(27.33,3.2) v3(28.68,7.65) v3(28.78,50.67) v3(29.1,52.67) v3(29.47,7.86) v3(30.57,26.82) v3(30.76,51.18) v3(31.62,51.49) v3(35.18,7.34) v4(8.89,27.53) v4(8.89,26.06) v4(10.37,27.53)
VBAT_IN:
  vias: v3(8.76,16.05) v3(9.14,14.91)
VCC_1V8: length 111.3
  TOP w0.229: v3(19.46,8.09) 19.18,8.37 C81.1 19.18,8.89 19.8,9.51 FB5.1 ; FB6.1 17.75,12.86 18,12.61 18,12.41 18.98,11.43 C83.1 19.51,11.12 v3(19.74,10.9) ; v3(29.65,22.13) 29.65,21.82 29.42,21.59 C73.1 28.33,21.59 28.2,21.72 FB1.1 ; v3(5.45,19.8) 5.45,19.33 5.21,19.09 5.21,17.65 4.52,16.97 4.52,11.3 5.14,10.68 5.42,10.68 5.44,10.67 6.76,10.67 6.76,10.67 7.62,10.67 v3(8.15,10.14) ; FB7.1 23.02,10.82 22.99,10.84 C89.1 21.84,10.55 v3(22.23,10.16) ; R124.1 5.89,53.64 6.1,53.86 v3(6.12,53.86) ; v2(27.47,23.69) 27.43,23.69 26.88,23.14 C75.1 26.38,22.96 26.29,23.05 25.5,23.05 25.27,22.83 25.27,22.14 25.41,22 FB2.1
  L03_SIG1 w0.229: v3(8.15,10.14) 8.15,9.93 9.09,8.99 10.19,8.99 11.35,10.16 16.59,10.16 17.5,9.25 21.16,9.25 21.74,9.83 21.89,9.83 v3(22.23,10.16)
  L03_SIG1 w0.381: v3(26.6,12.65) 26.6,13.33 26.49,13.44 26.49,17.87 27.47,18.84 v2(27.47,23.69)
  L04_SIG2 w0.229: v3(6.12,53.86) 5.05,52.79 5.05,47.47 4.56,46.98 4.56,44.97 5.11,44.42 5.11,27.97 4.86,27.72 4.86,26.98 5.08,26.76 5.08,24.65 5.84,23.89 5.84,22.05 6.25,21.64 6.25,20.13 5.92,19.8 v3(5.45,19.8) ; v2(33.91,28.56) 32.53,27.18 31.58,27.18 30.86,26.46 30.86,24.82 29.16,23.12 29.16,22.63 v3(29.65,22.13)
  L05_PWR w0.381: v3(29.65,22.13) 29.27,22.52 28.64,22.52 v2(27.47,23.69)
  BOTTOM w0.178: v2(33.91,28.56) 33.91,28.06 34.46,27.51 J17.3
  BOTTOM w0.229: FB4.1 19,12.98 19.48,12.5 19.48,11.15 v3(19.74,10.9)
  BOTTOM w0.305: R225.1 29.85,22.13 v3(29.65,22.13)
  BOTTOM w0.381: 23.16,11.45 22.23,10.52 v3(22.23,10.16)
  vias: v3(23.51,13.23)
VCC_3V3: length 56
  TOP w0.229: FB3.1 19.11,13.95 18.88,13.72 v3(18.24,13.72) 18.01,13.72 17.63,14.1 C77.1
  L03_SIG1 w0.508: v3(18.24,13.72) 19.57,12.38 v3(20.17,12.38)
  L05_PWR w0.254: v3(20.17,12.38) 20.47,12.08 20.47,11.02 20.17,10.72 20.17,9.41 19.03,8.27 19.03,7.49 19.53,6.99 20.73,6.99 21.08,7.34 21.59,7.34 21.79,7.14 29.56,7.14 29.83,7.41 31.69,7.41 33.35,9.07 33.35,9.63 32.08,10.9 32.08,15.44 31.36,16.16 31.36,17.26 31.89,17.78 31.89,22.15 32.28,22.54 32.28,22.57 32.89,23.18 34.21,23.18 35.33,24.3 35.33,27.97 34.85,28.46 34.85,29.06 35.07,29.29 35.07,29.64 34.76,29.96 33.95,29.96 33.34,29.35 33.34,28.36 32.64,27.66 v3(31.65,27.66)
  BOTTOM w0.178: v3(31.65,27.66) 31.9,27.91 J17.2
VCC_IN: length 6.8
  BOTTOM w0.229: 9.04,11.13 8.62,10.71 8.62,9.97 9.04,9.55 10.69,9.55 10.71,9.56 10.71,9.56 11.19,10.04 U29.5 ; v3(12.2,17.93) 12.24,17.93 12.27,17.96 12.39,17.96 12.54,18.12 C8.2 12.82,18.12 13.28,17.66 U26.1
  vias: v3(8.58,19.23) v3(9.11,18.93) v3(9.5,12.98) v3(9.98,11.84) v3(10.79,11.74) v3(11.1,15.93) v3(11.76,15.9) v3(21.79,9.25) v3(22.36,9.5)
VDD_1V8: length 129.8
  TOP w0.178: R85.2 22.1,23.14 22.2,23.24 22.73,23.24 22.91,23.42 22.91,24.25 22.73,24.42 21.72,24.42 v3(21.11,23.81) ; v3(16.41,15.23) 16.19,15.01 15.81,15.01 15.63,14.83 C5.2 15.58,14.58 U31.5 ; 16.66,21.26 16.66,21.23 17.14,20.75 18.35,20.75 18.6,21 U18.12 ; C200.1 29.77,50.62 30.33,50.06 30.33,48.88 30.01,48.57 Y4.P
  TOP w0.229: v3(0.79,7.93) 1.26,7.93 1.33,8 C66.1 ; v3(33.98,19.39) 33.84,19.52 33.72,19.64 U6.6 ; R76.1 30.81,21.04 v3(30.51,20.73) ; v3(16.82,46.84) 16.69,46.71 16.69,46.2 R196.2 ; v3(31.6,15.22) 31.6,15.6 31.85,15.85 C71.1 32.61,15.85 33.01,15.45 U22.3 ; C200.1 30.48,50.65 v3(30.76,50.37) ; U6.8 32.7,20.94 32.47,20.71 v3(32.47,20.45) ; v3(6.99,33.25) 6.91,33.32 C99.1 6.94,33.97 7.24,33.66 7.8,33.66 8.11,33.97 9.53,33.97 U3.D1 ; v3(12.07,40.08) 12.12,40.14 C96.1 C97.1 ; v1(13.26,32.55) 13.26,32.57 13.03,32.8 U3.E4 ; R9.1 12.62,11.3 12.4,11.53 v3(12.4,11.69) ; R5.2 v3(14.21,11.52) ; R6.1 12.42,9.78 12.17,9.53 v3(11.35,9.53) ; U3.B4 12.76,35.8 v1(13.29,36.32) ; v3(6.55,51.69) 6.2,52.05 R224.1 ; v3(15.7,28.17) 15.72,28.15 16.18,28.15 C67.1 16.34,27.6 16.6,27.34 16.81,27.34 U20.C1 ; v3(18.28,11.42) 18.27,11.42 17.95,11.09 R2.1 ; v3(16.42,12.5) 16.29,12.5 16.06,12.27 R8.2 ; U18.8 17.02,22.98 v3(16.96,23.04) 16.63,22.71 16.63,21.29 16.66,21.26 ; R112.2 R114.2 7.41,37.89 v3(7.57,38.05) ; U18.5 19.6,23.6 19.83,23.83 20.02,23.83 20.25,24.05 C63.2 20.59,24.33 v3(21.11,23.81) ; U20.B2 U20.B3 17.45,25.67 17.37,25.59 C68.1 18.16,25.2 v3(18.49,24.86) 18.45,24.82 C64.1
  TOP w0.381: v3(32.25,44.54) 32.25,43.99 32.45,43.79 32.45,35.94 31.92,35.41 v3(31.37,35.41) ; v3(11.96,29.67) 12.08,29.78 12.08,30.58 11.1,31.56 v3(11.1,31.85) 12.8,31.85 13.18,32.23 13.18,32.48 v1(13.26,32.55)
  L03_SIG1 w0.381: v3(16.42,12.5) 16.81,12.12 16.81,12.12 17.56,11.37 18.22,11.37 v3(18.28,11.42)
  L04_SIG2 w0.229: 29.31,7.14 29.59,7.14 30.08,7.62 v3(30.08,7.89)
  L04_SIG2 w0.381: v3(32.47,20.45) 32.47,20.45 31.37,20.45 31.09,20.73 v3(30.51,20.73) 30.51,20.19 30.19,19.86 29.92,19.86 29.64,19.59 29.64,17.58 31.21,16.01 31.21,15.6 v3(31.6,15.22) 31.6,14.25 26.88,9.54 26.88,7.47 27.22,7.14 29.31,7.14
  L04_SIG2 w0.635: v3(6.55,51.69) 6.55,50.62 9.17,48.01 12.48,48.01 v3(13.45,48.98)
  BOTTOM w0.229: U8.2 0.8,7.91 v3(0.79,7.93) ; v3(28.25,40.67) 28.61,41.03 Y3.4 ; Y3.1 31.97,41.88 31.66,42.19 C61.1 31.29,43.81 31.31,43.82 R79.1 v3(32.25,44.54) ; v3(12.07,40.08) 12.3,39.84 U4.B4 ; R204.1 8.01,47.51 7.49,48.03 v3(6.63,48.03) ; U7.4 U7.2 32.12,8.17 31.75,7.8 C70.1 30.74,7.8 30.66,7.88 30.56,7.88 30.55,7.89 v3(30.08,7.89) ; v1(13.29,36.32) 13.79,35.82 16.17,35.82 16.76,35.23 C98.1 R208.2 ; R205.1 7.67,45.2 7.06,44.59 v3(7.06,44.12) ; R123.2 10.64,32.08 10.87,31.85 v3(11.1,31.85) ; v3(13.45,48.98) 13.47,49 13.52,49 13.6,49.08 C204.1 14.65,49.08 14.79,48.93 U40.8 ; v3(33.98,19.39) 34.45,19.39 34.75,19.68 C62.1 ; J5.1 34.42,31.95 33.9,32.47 32.25,32.47 32.02,32.7 R195.2 R194.2 R193.2 R192.2 31.85,35.49 31.84,35.48 31.45,35.48 v3(31.37,35.41) ; C65.1 33.03,20.57 32.9,20.45 32.48,20.45 v3(32.47,20.45) ; R203.2 30.02,50.12 30.26,50.37 v3(30.76,50.37)
  vias: v3(6.55,22.58) v3(6.63,21.94)
VDD_3V3: length 57.9
  TOP w0.178: U25.23 26.32,43.43 26.21,43.54 25.96,43.54 25.82,43.4 U25.22
  TOP w0.229: v3(25.45,41.61) 25.71,41.35 C95.1 26.24,41.84 26.32,41.92 U25.23 ; v3(4.62,9.98) 4.62,8.88 3.85,8.1 R159.2
  TOP w0.381: C107.1 6.25,24.92 v3(6.02,24.69) ; v3(19.33,27.19) 19.87,27.19 20.41,26.65 22.19,26.65 23.76,25.08 R197.2 ; v3(5.26,23.29) 5.26,21.97 J14.19
  L03_SIG1 w0.305: J14.19 4.12,21.81 ; J14.19 5.1,20.83 ; J14.19 4.12,19.85
  L05_PWR w0.381: v3(21.34,56.61) 19.58,56.61 18.06,55.09 v3(18.06,54.51)
  L05_PWR w0.508: v3(17.69,28.29) 16.89,27.48 12.09,27.48 8.28,31.29 v3(8.28,33.4)
  BOTTOM w0.229: v3(18.06,54.51) 18.53,54.51 18.87,54.85 R206.2 ; v3(25.45,41.61) 25.78,41.94 25.78,42.6 26.18,43 C94.1 ; R206.2 18.42,56.34 18.39,56.31 R153.2 ; R206.2 18.87,56.73 18.87,57.38 18.65,57.6 J7.2 ; v3(18.64,49.56) 18.27,49.18 C203.2 16.52,49.18 16.28,48.93 U40.1 ; v3(8.28,33.4) 8.28,32.93 8.08,32.73 8.08,32.21 8.05,32.18 C109.1 8.08,32.13 8.08,31.72 8.31,31.49 C110.1 8.31,30.88 8.64,30.55 U28.28 ; v3(15.39,46.53) 14.76,46.53 14.76,46.53 R217.2 ; R188.2 19.21,43.03 18.36,43.88 v3(18.36,46.2) ; R207.2 21.06,56.34 v3(21.34,56.61)
  vias: v3(18.72,28.4) v3(23.19,10.06)
VDD_5V: length 61.3
  TOP w0.178: R210.2 29.08,11.6 28.45,10.97 R209.2
  TOP w0.229: v3(15.91,19.49) 15.87,19.45 C6.2 15.87,17.59 15.96,17.5 U15.6 ; U21.12 13.97,9.43 13.92,9.39 13.48,9.39 13.11,9.01 C12.1 ; R209.2 28.45,9.9 v3(29.21,9.14) ; v3(32.34,9.49) 32.73,9.88 34.21,9.88 34.46,10.12 LED3.4
  TOP w0.305: v3(15.98,8.94) 15.98,8.33 15.97,8.33 15.97,8.3 15.85,8.17 15.85,3.18 16.51,2.52 v3(16.51,1.88)
  L05_PWR w0.254: v2(34.54,29.5) 34.39,29.35 34.39,28.27 34.87,27.78 34.87,24.48 34.02,23.63 32.7,23.63 32.19,23.12 31.71,23.12 31.43,22.84 31.43,17.97 30.91,17.45 30.91,11.41 32.34,9.98 v3(32.34,9.49)
  L05_PWR w0.381: 28.35,9.48 28.83,9.48 29.13,9.17 29.18,9.17 v3(29.21,9.14) 29.21,8.89 29.59,8.51 30.44,8.51 31.32,9.39 31.33,9.39 31.43,9.49 v3(32.34,9.49)
  BOTTOM w0.178: 5.98,27.81 6.46,27.81 U28.21 ; v2(34.54,29.5) 34.54,28.09 34.72,27.91 J17.1
  BOTTOM w0.229: C102.1 6.38,30.74 6.12,30.48 6.12,29.48 6.32,29.28 U28.24 ; C102.1 6.38,31.22 5.51,32.08 5.51,33.33 6.4,34.21 v3(7.44,34.21) ; C102.1 5.82,31.19 v3(5.64,31.01) ; R190.2 R174.2 16.99,2.36 v3(16.51,1.88) ; 5.98,27.81 5.97,27.83 5.55,27.83 v3(5.54,27.84)
  BOTTOM w0.381: U13.9 14.82,24.91 14.38,24.46 C30.1 13.69,23.88 13.52,24.05 v3(13.51,24.05)
  vias: v3(3.15,58.98) v3(3.15,57.94) v3(3.15,56.92) v3(12.63,20.03) v3(13.46,21.69) v3(14.15,8.94) v3(16.5,8.58) v3(17.04,24.67) v3(17.35,23.52) v3(20.29,8.13)
VDDA_RADAR: length 3.8
  TOP w0.229: U5.J1 24.43,18.85 24.77,19.19 C76.1 24.39,21.21 FB2.2
VDDD_RADAR: length 4.2
  TOP w0.229: FB1.2 26.62,21.09 26.42,20.89 C74.1 26.42,20.47 26.05,20.11 25.74,20.11 25.3,19.66 25.3,19.11 24.93,18.74 U5.H1
VDDIO_RADIO: length 6.3
  TOP w0.229: U25.11 20.63,44.19 20.46,44.01 C93.1 19.59,44.01 v3(19.41,44.2) ; R108.1 19.23,44.81 v3(19.15,44.88) ; v3(19.74,49.25) R104.1 R103.1 19.74,46.82 v3(19.56,46.64) 19.79,46.4 R105.1
VDDLF_RADAR: length 5
  TOP w0.178: U5.M3 22.47,17.39 21.95,16.87 20.5,16.87 20.4,16.77 C78.1
  TOP w0.229: FB3.2 19.12,15.36 19.62,15.86 19.62,16.06 20.02,16.46 C78.1
VDDPLL_RADAR: length 6.4
  TOP w0.229: FB6.2 18.77,12.89 19.85,13.97 19.85,14.87 20.41,15.42 C84.1 20.87,15.42 21.91,16.46 22.11,16.46 22.54,16.89 U5.M4
VDDRF_RADAR: length 22.3
  TOP w0.178: v3(19.31,18.41) 19.92,18.41 20.03,18.29 C86.1 20.38,18.09 20.55,17.91 21.75,17.91 22.23,18.39 U5.M1
  TOP w0.229: FB7.2 23.65,11.84 23.68,11.8 C85.1 24.76,11.8 24.99,12.03 C87.1 ; C87.1 25.33,12.25 25.68,12.6 25.68,12.98 25.43,13.24 U5.G9 ; C87.1 C88.1 26.13,13.75 25.93,13.96 U5.F9
  TOP w0.254: v3(21.93,13.26) 22.11,13.26 22.15,13.21 22.53,13.21 23.07,12.66 FB7.2
  L03_SIG1 w0.229: v3(19.31,18.41) 18.98,18.07 18.98,14.58 20.63,12.92 21.59,12.92 v3(21.93,13.26)
VDDVCO_RADAR: length 7
  TOP w0.229: U5.M6 22.65,15.89 22.17,15.41 22.17,15.06 20.79,13.67 C82.1 21.02,12.04 21.22,11.84 21.22,11.15 20.6,10.53 FB5.2
A_IO_P13_0: length 18.5
  TOP w0.15: v1(24.57,33.36) 24.57,33.34 U1.G8
  L03_SIG1 w0.157: v2(33.78,29.1) 32.78,28.1 32.78,25.55 v2(31.73,24.5)
  BOTTOM w0.089: 31.17,30.76 31.14,30.76 30.94,30.96 30.94,31.77 30.14,32.56 25.37,32.56 v1(24.57,33.36)
  BOTTOM w0.15: v2(33.78,29.1) 33.78,29.51 33.75,29.54 33.75,29.7 32.69,30.76 31.17,30.76 ; J17.20 32.1,24.31 31.91,24.5 v2(31.73,24.5)
A_IO_P13_1: length 17.6
  TOP w0.089: v2(29.56,33.24) 29.83,32.97 29.83,32.88 31.17,31.54
  TOP w0.15: v2(33.16,24.72) 33.25,24.72 34.41,25.87 34.41,27.44 34.26,27.59 33.38,27.59 32.28,28.68 32.28,29.01 32.27,29.02 32.27,30.43 31.17,31.54 ; U1.G9 v1(25.25,33.3)
  L04_SIG2 w0.089: v2(29.56,33.24) 29.19,33.24 28.96,33.01 27.09,33.01 26.44,33.66 25.61,33.66 v1(25.25,33.3)
  BOTTOM w0.15: J17.18 32.87,24.71 32.91,24.67 33.12,24.67 33.16,24.7 v2(33.16,24.72)
A_IO_P13_2: length 15
  TOP w0.089: U1.G10 26.56,32.64 29.57,32.64 30.48,31.73 30.48,30.71 v2(31.09,30.1)
  L03_SIG1 w0.089: 31.17,30.55 31.09,30.47 v2(31.09,30.1)
  L03_SIG1 w0.157: v2(31.71,25.1) 32,25.39 32,25.4 32.31,25.71 32.31,26.41 32.52,26.61 32.52,29.12 32.31,29.32 32.31,30.5 32.15,30.66 31.27,30.66 31.17,30.55
  BOTTOM w0.15: J17.16 31.72,25.11 v2(31.71,25.1)
A_IO_P13_3: length 16.5
  TOP w0.089: 31.17,32.72 31.16,32.72 30.99,32.89 30.58,32.89 29.81,33.66 U1.F15
  TOP w0.15: v2(31.72,25.66) 32.13,25.66 32.26,25.53 32.26,24.64 32.59,24.31 33.32,24.31 34.66,25.64 34.66,27.65 34.45,27.86 33.45,27.86 32.53,28.78 32.53,29.11 32.53,29.12 32.53,30.54 32.49,30.57 32.49,30.86 31.67,31.67 31.67,32.21 31.17,32.72
  BOTTOM w0.15: J17.14 31.89,25.51 31.75,25.66 31.73,25.66 v2(31.72,25.66)
A_IO_P13_4: length 14.1
  TOP w0.089: v2(29.98,33.98) 30.61,33.35 30.94,33.35 31.17,33.12
  TOP w0.15: U1.G11 27.13,33.3 27.18,33.34 v1(27.22,33.34) ; 31.17,33.12 32,32.28 32,31.73 32.8,30.93 32.8,29.84 32.93,29.71 v2(32.93,29.3)
  L03_SIG1 w0.089: v1(27.22,33.34) 27.6,32.97 28.52,32.97 28.63,33.08 28.71,33.08 29.61,33.98 v2(29.98,33.98)
  BOTTOM w0.15: J17.12 32.86,25.91 33.1,26.16 33.1,26.87 33.29,27.06 33.29,27.9 33.29,27.9 33.29,28.25 33.26,28.28 33.26,28.41 32.93,28.74 v2(32.93,29.3)
A_IO_P13_5: length 9.5
  TOP w0.089: v2(31.85,29.41) 31.59,29.68 31.45,29.82 31.45,30.3 30.84,30.91 30.84,31.62 29.63,32.83 28.97,32.83 U1.G14
  L03_SIG1 w0.157: v2(31.85,29.41) 32.26,29.01 32.26,26.72 31.75,26.22 v2(31.75,26.22)
  BOTTOM w0.15: v2(31.75,26.22) 31.75,26.22 31.85,26.31 J17.10
A_IO_P13_6: length 11.6
  TOP w0.15: U1.H11 v1(27.17,32.04)
  L03_SIG1 w0.089: 31.17,29.62 31.17,29.62 30.96,29.41 30.96,29.11 31.17,28.9
  L03_SIG1 w0.157: 31.17,29.62 31.22,29.62 31.54,29.94 31.58,29.94 v2(31.87,30.23) ; v2(31.74,26.79) 31.74,26.79 31.72,26.82 31.72,27.04 31.24,27.52 31.24,28.83 31.17,28.9
  BOTTOM w0.089: 31.17,30.51 31.04,30.51 30.76,30.79 30.76,31.7 30.07,32.39 27.52,32.39 v1(27.17,32.04)
  BOTTOM w0.15: J17.8 31.83,26.71 31.76,26.79 v2(31.74,26.79) ; v2(31.87,30.23) 31.54,30.23 31.26,30.51 31.17,30.51
A_IO_P13_7: length 7.5
  TOP w0.15: v2(31.32,29.26) 30.23,30.35 30.23,31.47 29.65,32.05 29.65,32.16 U1.H15
  BOTTOM w0.15: v2(31.32,29.26) 31.32,28.85 30.89,28.42 30.89,27.56 31.22,27.22 31.89,27.22 32,27.11 J17.6
A_IO_P15_0: length 7.2
  TOP w0.089: 31.62,28.42 30.94,29.11 30.94,29.28 30.17,30.05 29.8,30.05 U1.L15
  TOP w0.15: 31.62,28.42 31.65,28.42 31.67,28.4 32.21,28.4 33.47,27.14 v2(33.98,27.14)
  BOTTOM w0.15: v2(33.98,27.14) 34.39,27.14 34.41,27.11 J17.5
A_IO_P15_1: length 10.3
  TOP w0.089: v1(28.47,30.74) U1.K13
  BOTTOM w0.089: v1(28.47,30.74) 28.78,30.42 29.26,30.42 30.06,29.62 31.11,29.62 31.15,29.66 31.17,29.66
  BOTTOM w0.15: J17.7 33.91,26.71 33.89,26.73 33.82,26.73 33.54,27 33.54,28 33.54,28.01 33.54,28.35 33.51,28.38 33.51,28.52 33.34,28.69 33.34,29.48 32.99,29.82 31.5,29.82 31.38,29.66 31.17,29.66
A_IO_P15_2: length 7.4
  TOP w0.089: U1.M15 30.21,29.76 30.76,29.21 30.76,28.93 31.17,28.52
  TOP w0.15: v2(33.57,26.4) 33.29,26.69 33.29,26.92 32.12,28.09 31.59,28.09 31.17,28.52
  BOTTOM w0.15: J17.9 34.37,26.31 34.28,26.4 v2(33.57,26.4)
A_IO_P15_3: length 19.4
  TOP w0.15: v1(25.86,30.75) 25.85,30.75 U1.K9
  L03_SIG1 w0.089: v1(25.86,30.75) 25.99,30.75 26.34,30.4 26.38,30.4 26.38,30.4 27.02,30.4 27.03,30.39 27.35,30.39 27.49,30.24 27.49,29.94 27.72,29.71 27.97,29.71 28.17,29.51 28.17,28.63 28.37,28.43 28.85,28.43 29.18,28.09 29.18,27.87 30.21,26.84 30.21,26.67 30.45,26.43
  L03_SIG1 w0.157: v2(33.9,25.95) 34.65,25.21 34.65,24.13 34.09,23.57 33.36,23.57 32.14,22.35 31.64,22.35 31,23 31,23.77 30.79,23.98 30.79,26.09 30.45,26.43
  BOTTOM w0.15: v2(33.9,25.95) 34.31,25.95 34.35,25.91 J17.11
A_IO_P15_4: length 7.2
  TOP w0.089: U1.N15 29.58,29.11 31.17,27.52 31.17,27.48
  TOP w0.15: 31.17,27.48 31.43,27.22 31.96,27.22 v2(33.35,25.83)
  BOTTOM w0.15: v2(33.35,25.83) 33.64,25.54 33.69,25.54 33.72,25.51 J17.13
A_IO_P15_5: length 15.5
  TOP w0.15: U1.K10 26.52,30.74 v1(26.52,30.74)
  L03_SIG1 w0.089: v1(26.52,30.74) 26.85,31.06 27.95,31.06 28.14,30.87 28.14,30.84 28.14,30.84 28.14,30.6 28.33,30.41 28.6,30.41 28.79,30.22 28.79,29.95 29.03,29.72 29.51,29.72 29.88,29.36 29.88,28.72 30.17,28.43 30.8,28.43 31.02,28.22 31.02,27.33 31.17,27.18
  L03_SIG1 w0.157: v2(33.17,25.3) 31.89,24.02 31.61,24.02 31.3,24.32 31.3,27.04 31.17,27.18
  BOTTOM w0.15: J17.15 34.81,25.11 34.66,25.26 33.62,25.26 33.58,25.3 v2(33.17,25.3)
A_IO_P15_6: length 11.3
  TOP w0.089: v1(29.73,28.11) 29.72,28.12 29.72,28.19 U1.P15
  BOTTOM w0.089: v1(29.73,28.11) 30.07,27.78 30.07,26.65 30.13,26.59
  BOTTOM w0.15: 30.13,26.59 30.38,26.34 30.58,26.34 31.19,25.73 31.19,23.26 31.34,23.12 32.69,23.12 33.1,23.52 33.1,24.08 33.57,24.55 33.57,24.7 33.81,24.94 34.4,24.94 34.63,24.71 J17.17
A_IO_P15_7: length 15.2
  TOP w0.15: v1(27.17,30.72) 27.17,30.74 U1.K11
  L03_SIG1 w0.089: v1(27.17,30.72) 27.32,30.72 27.48,30.56 27.5,30.56 27.65,30.41 27.95,30.41 28.14,30.22 28.14,29.9 28.28,29.76 28.63,29.76 29.46,28.93 29.46,28.31 29.36,28.21 29.36,27.94 30.09,27.21 30.71,27.21 31.05,26.87 31.05,26.59
  L03_SIG1 w0.157: v2(34.21,24.51) 33.92,24.8 33.75,24.8 32.19,23.24 31.51,23.24 31.29,23.46 31.29,23.91 31.05,24.15 31.05,26.59
  BOTTOM w0.15: v2(34.21,24.51) 34.27,24.45 34.32,24.45 34.47,24.31 J17.19
ALT_SER_INT_CONFIG_1: length 5.4
  TOP w0.15: R76.2 30.79,23.51 30.77,23.51 30.07,24.21 30.07,24.34 TP66.1 30.07,25.6 30.07,27.18 U1.R15
ALT_SER_INT_CONFIG_2: length 26.1
  TOP w0.15: U1.M12 27.83,29.42 v1(27.83,29.39)
  L03_SIG1 w0.089: v2(30.41,28.8) 30.67,29.06 30.67,30.5 31.17,30.99
  L03_SIG1 w0.157: 31.17,30.99 31.27,31.09 31.39,31.09 33.44,33.13 33.44,43.93 v2(31.8,45.57)
  BOTTOM w0.089: v2(30.41,28.8) 29.96,28.8 29.01,29.75 28.19,29.75 v1(27.83,29.39)
  BOTTOM w0.15: R79.2 TP65.1 31.17,45.8 31.4,45.57 v2(31.8,45.57)
AMIC1_CTB_INN: length 42.6
  TOP w0.102: v1(28.49,31.99) 28.49,32 28.49,32.02 U1.H13
  L03_SIG1 w0.089: v1(28.49,31.99) 28.52,32.02 28.52,32.05 28.71,32.25 28.82,32.25 28.93,32.36 30.15,32.36 30.77,32.98 31.61,32.98 32.14,33.52 32.14,34.57 32.32,34.75 32.32,35.05 32.14,35.23 32.14,35.54 32.32,35.72 32.32,36.02 32.14,36.2 32.14,36.51 32.19,36.55 32.19,36.57 ; 30.28,39.45 31.22,38.5 31.22,37.94 31.24,37.94
  L03_SIG1 w0.102: 32.19,36.57 32.19,36.99 31.93,37.26 31.93,37.51 31.71,37.73 31.46,37.73 31.24,37.94 ; 30.28,39.45 30.13,39.59 30.13,41.43 30.32,41.61 30.32,41.92 30.13,42.1 30.13,42.4 30.32,42.58 30.32,42.89 30.13,43.07 30.13,43.37 29.01,44.5 29.01,44.8 29.19,44.98 29.19,45.29 29.01,45.47 29.01,45.77 29.19,45.95 29.19,46.26 29.01,46.44 29.01,46.74 29.19,46.92 29.19,47.23 29.01,47.41 29.01,48.28 29.19,48.46 29.19,48.77 29.01,48.95 29.01,50 29.42,50.41 29.42,50.95 28.54,51.82 28.54,52.08 28.33,52.29 28.07,52.29 27.66,52.71 27.66,52.96 27.44,53.18 27.19,53.18 26.97,53.39 25.81,53.39 25.63,53.57 25.32,53.57 25.14,53.39 24.13,53.39 23.95,53.57 23.65,53.57 23.47,53.39 17.81,53.39 17.5,53.08 17.5,52.59 17.4,52.49 v2(17.26,52.49)
  BOTTOM w0.102: R132.2 15.67,53.07 16.12,53.07 C121.2 16.56,53.07 17.42,53.07 17.53,52.97 17.53,52.75 v2(17.26,52.49)
AMIC1_CTB_INP: length 42.6
  TOP w0.102: U1.H10 26.46,32.1 26.5,32.1 v1(26.54,32.06)
  L03_SIG1 w0.089: 30.97,37.82 30.95,37.83 30.95,38.39 30.17,39.17 30.16,39.17 30.1,39.24 30.09,39.24 30.08,39.25 ; v1(26.54,32.06) 26.92,32.44 28.74,32.44 28.85,32.55 30.07,32.55 30.69,33.17 31.53,33.17 31.95,33.6 31.95,36.51 31.91,36.55 31.91,36.57
  L03_SIG1 w0.102: 30.97,37.82 31.91,36.88 31.91,36.57 ; 30.08,39.25 29.85,39.47 29.85,43.26 28.73,44.38 28.73,50.12 29.13,50.53 29.13,50.83 26.86,53.11 17.93,53.11 17.78,52.97 17.78,52.73 v2(18.03,52.49)
  BOTTOM w0.102: v2(18.03,52.49) 17.78,52.74 17.78,53.08 17.53,53.33 16.56,53.33 C116.1 16.12,53.33 15.67,53.33 R128.2 R227.2
AMIC1_CTB_OUT: length 47
  TOP w0.15: U1.H9 v1(25.87,32.04)
  L03_SIG1 w0.089: 29.54,39.29 30.07,38.76 30.33,38.76 30.73,38.36 30.73,37.57 30.91,37.39 30.91,34.9 31.17,34.64 31.17,33.74 30.85,33.43 30.54,33.43 29.84,32.73 28.78,32.73 28.66,32.61 26.45,32.61 v1(25.87,32.04)
  L03_SIG1 w0.157: v2(11.98,48.95) 11.98,49.36 11.99,49.37 11.99,49.48 12.73,50.22 14.6,50.22 v2(15.01,50.62) 15.76,51.37 21.29,51.37 21.41,51.49 27.58,51.49 28.35,50.72 28.35,44.36 29.27,43.44 29.27,39.57 29.54,39.29
  BOTTOM w0.15: 11.98,48.69 12.1,48.57 C122.1 ; 11.98,48.69 v2(11.98,48.95) ; 11.98,48.69 11.83,48.54 R133.2 ; C121.1 15.47,52.3 15.01,51.84 v2(15.01,50.62)
AMIC1_CTB_REF: length 45.8
  TOP w0.15: v1(26.55,31.4) 26.53,31.41 26.49,31.41 U1.J10
  L04_SIG2 w0.089: 31.35,34.29 31.17,34.11 31.17,33.12 30.4,32.36 28.4,32.36 28.17,32.13 28.17,31.86 28.02,31.71 26.86,31.71 v1(26.55,31.4) ; 29.77,39.29 30.33,38.74 30.56,38.74 30.96,38.33 30.96,38.01
  L04_SIG2 w0.157: 30.96,38.01 30.96,37.97 30.99,37.95 30.99,35.16 31.35,34.8 31.35,34.29 ; 29.77,39.29 29.08,39.98 29.08,49.79 27.36,51.51 22.91,51.51 21.67,50.27 19.92,50.27 19.76,50.43 19.76,54.05 18.11,55.7 15.01,55.7 v2(13.84,54.53)
  BOTTOM w0.15: R227.1 v2(13.84,54.53)
AMIC2_CTB_INN: length 44
  TOP w0.102: U1.J15 29.77,31.39 v1(29.78,31.39)
  L03_SIG1 w0.089: 32.67,38.94 32.67,38.93 32.71,38.88 32.71,38.26 32.53,38.08 32.53,37.77 32.71,37.59 32.71,36.94 32.53,36.75 32.53,36.45 32.71,36.27 32.71,35.67 32.53,35.48 32.53,35.18 32.71,35 32.71,34.64 32.53,34.46 32.53,34.15 32.71,33.97 32.71,33.67 31.77,32.73 30.8,32.73 30.49,32.42 30.49,31.4 30.4,31.31 30.27,31.31 30.2,31.39 v1(29.78,31.39)
  L03_SIG1 w0.102: 32.67,38.94 32.67,39.49 32.49,39.67 32.49,39.98 32.67,40.16 32.67,40.46 32.49,40.64 32.49,40.95 32.67,41.13 32.67,41.52 32.49,41.7 32.49,42.01 32.67,42.19 32.67,42.49 32.44,42.72 32.18,42.72 31.96,42.94 31.96,43.2 31.75,43.41 31.49,43.41 31.28,43.63 31.28,43.88 31.06,44.1 30.81,44.1 30.59,44.31 30.59,44.57 30.38,44.78 30.12,44.78 29.91,45 29.91,45.25 29.69,45.47 29.69,46.76 29.51,46.94 29.51,47.25 29.69,47.43 29.69,47.73 29.51,47.91 29.51,48.22 29.69,48.4 29.69,49.1 29.51,49.28 29.51,49.58 29.74,49.82 29.74,51.15 29.56,51.33 29.56,51.64 29.74,51.82 29.74,53.09 29.5,53.33 29.24,53.33 29.03,53.55 29.03,53.81 28.65,54.18 28.32,54.18 28.14,54 27.83,54 27.65,54.18 27.35,54.18 27.17,54 26.86,54 26.68,54.18 26.38,54.18 26.2,54 25.89,54 25.71,54.18 25.41,54.18 25.23,54 24.92,54 24.74,54.18 24.44,54.18 24.26,54 23.95,54 23.77,54.18 23.37,54.18 23.19,54 22.89,54 22.71,54.18 22.4,54.18 22.22,54 21.92,54 21.73,54.18 21.39,54.18 21.21,54 20.91,54 20.73,54.18 20.42,54.18 19.99,54.61 18.93,54.61 18.83,54.51 18.83,54.11 v2(19.08,53.86)
  BOTTOM w0.102: R141.2 20.38,53.63 20.12,53.37 19.87,53.37 C129.2 19.41,53.38 18.94,53.38 18.84,53.48 18.84,53.63 v2(19.08,53.86)
AMIC2_CTB_INP: length 48.4
  TOP w0.102: v1(25.88,31.39) 25.87,31.39 U1.J9
  L03_SIG1 w0.089: v1(25.88,31.39) 26.21,31.72 27.03,31.72 27.03,31.71 27.95,31.71 28.14,31.52 28.14,31.25 28.33,31.06 28.71,31.06 28.8,30.96 28.8,30.63 28.99,30.44 29.26,30.44 29.45,30.63 29.45,30.89 29.61,31.05 30.2,31.05 30.27,31.12 30.48,31.12 30.68,31.32 30.68,32.34 30.88,32.54 31.85,32.54 32.9,33.59 32.9,38.87 32.95,38.92 32.95,38.94
  L03_SIG1 w0.102: 32.95,38.94 32.95,42.61 29.97,45.59 29.97,49.65 30.03,49.7 30.03,53.2 28.77,54.46 20.54,54.46 20.11,54.89 18.82,54.89 18.55,54.62 18.55,54.11 v2(18.31,53.86)
  BOTTOM w0.102: R228.2 20.45,52.37 20.38,52.45 R137.2 20.12,53.11 19.84,53.11 C124.1 19.41,53.13 18.84,53.13 18.59,53.38 18.59,53.59 v2(18.31,53.86)
AMIC2_CTB_OUT: length 39.8
  TOP w0.15: v1(29.85,30.71) 29.79,30.71 U1.K15
  L03_SIG1 w0.089: v1(29.85,30.71) 30.32,30.71 30.86,31.25 30.86,31.38 31.06,31.58 31.17,31.58
  L03_SIG1 w0.157: v2(22.68,54.84) 28.93,54.84 31.19,52.58 31.19,44.88 33.18,42.9 33.18,33.24 31.52,31.58 31.17,31.58
  BOTTOM w0.15: C129.1 C130.1 ; C130.1 23.7,54.15 23.73,54.18 R142.2 ; C130.1 22.76,54.71 22.68,54.79 v2(22.68,54.84)
